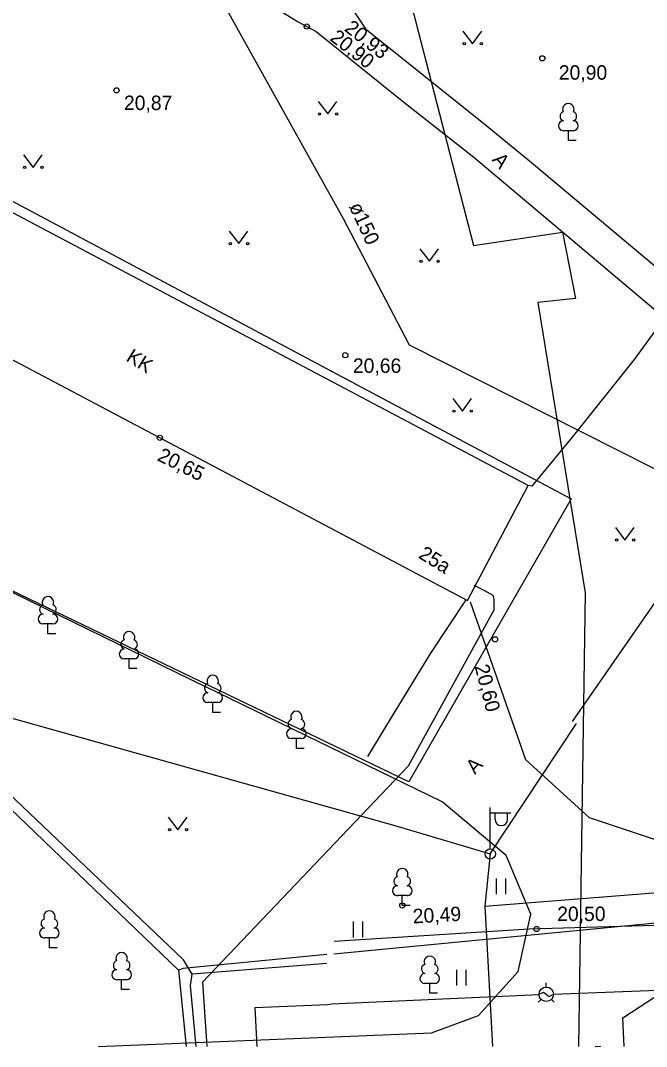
# Model space of a CAD drawing. Extents: x 714038 to 714279, y 6589845 to 6590041.
# Drawn here: x 714075.51 to 714105.82, y 6589845.18 to 6589894.87 of the extents above; entities that cross this region are included whole.
import ezdxf

# ---------------------------------------------------------------- set-up
doc = ezdxf.new("R2010")
doc.units = 0
for name, color, linetype in [('HALJASTUS', 7, 'Continuous'), ('HOONE', 7, 'Continuous'), ('KORGUS', 7, 'Continuous'), ('MPKAABEL', 7, 'Continuous'), ('POST', 7, 'Continuous'), ('PUU', 7, 'Continuous'), ('SITRASS', 7, 'Continuous'), ('TEE', 7, 'Continuous'), ('TORU NR', 7, 'Continuous'), ('TTRASS', 7, 'Continuous'), ('Слой 1', 7, 'Continuous')]:
    doc.layers.add(name, color=color, linetype=linetype)

msp = doc.modelspace()

# ---------------------------------------------------------------- linework, layer by layer
at = {"layer": 'HALJASTUS'}
for p, q in [((714096.937, 6589894.357), (714097.4, 6589893.75)), ((714097.4, 6589893.75), (714097.846, 6589894.357)), ((714089.927, 6589890.957), (714090.39, 6589890.35)), ((714090.39, 6589890.35), (714090.836, 6589890.957)), ((714075.657, 6589888.367), (714076.12, 6589887.76)), ((714076.12, 6589887.76), (714076.566, 6589888.367)), ((714085.617, 6589884.677), (714086.08, 6589884.07)), ((714086.08, 6589884.07), (714086.526, 6589884.677)), ((714094.847, 6589883.817), (714095.31, 6589883.21)), ((714095.31, 6589883.21), (714095.756, 6589883.817)), ((714096.447, 6589876.557), (714096.91, 6589875.95)), ((714096.91, 6589875.95), (714097.356, 6589876.557)), ((714104.317, 6589870.317), (714104.78, 6589869.71)), ((714104.78, 6589869.71), (714105.226, 6589870.317)), ((714082.667, 6589856.287), (714083.13, 6589855.68)), ((714083.13, 6589855.68), (714083.576, 6589856.287)), ((714098.549, 6589853.318), (714098.549, 6589852.557)), ((714099.004, 6589853.318), (714099.004, 6589852.557)), ((714091.624, 6589851.226), (714091.624, 6589850.465)), ((714092.079, 6589851.226), (714092.079, 6589850.465)), ((714096.617, 6589848.892), (714096.617, 6589848.131)), ((714097.072, 6589848.892), (714097.072, 6589848.131))]:
    msp.add_line(p, q, dxfattribs=at)
msp.add_lwpolyline([(714092.33, 6589859.23), (714093.48, 6589861.11), (714095.38, 6589864.23), (714097.1, 6589866.81)], dxfattribs=at)
for centre in [(714096.999, 6589893.75), (714097.828, 6589893.75), (714089.989, 6589890.35), (714090.818, 6589890.35), (714075.719, 6589887.76), (714076.548, 6589887.76), (714085.679, 6589884.07), (714086.508, 6589884.07), (714094.909, 6589883.21), (714095.738, 6589883.21), (714096.509, 6589875.95), (714097.338, 6589875.95), (714104.379, 6589869.71), (714105.208, 6589869.71), (714082.729, 6589855.68), (714083.558, 6589855.68)]:
    msp.add_circle(centre, 0.055, dxfattribs=at)
at = {"layer": 'HOONE'}
for p, q in [((714100.973, 6589848.058), (714100.973, 6589848.255)), ((714100.623, 6589847.706), (714100.834, 6589847.812)), ((714100.834, 6589847.812), (714101.112, 6589847.604)), ((714101.112, 6589847.604), (714101.323, 6589847.71)), ((714100.726, 6589847.461), (714100.586, 6589847.321)), ((714101.22, 6589847.461), (714101.36, 6589847.321))]:
    msp.add_line(p, q, dxfattribs=at)
for points in [[(714078.09, 6589905.88), (714078.71, 6589905.51), (714082.61, 6589900.59), (714091.14, 6589885.28), (714094.34, 6589879.16), (714119.53, 6589866.44), (714125.14, 6589863.75), (714152.793, 6589849.501)], [(714067.9, 6589889.39), (714064.95, 6589883.81), (714097.15, 6589866.78), (714100.1, 6589872.35), (714067.9, 6589889.39)], [(714101.323, 6589847.721), (714118.1, 6589848.36), (714137.92, 6589849.09), (714152.448, 6589849.676)], [(714086.964, 6589845.18), (714086.87, 6589847.07), (714090.375, 6589847.215), (714090.58, 6589847.238), (714100.623, 6589847.692)]]:
    msp.add_lwpolyline(points, dxfattribs=at)
msp.add_circle((714100.973, 6589847.708), 0.35, dxfattribs=at)
at = {"layer": 'KORGUS'}
for centre in [(714089.38, 6589894.58), (714100.78, 6589893.04), (714080.16, 6589891.49), (714091.24, 6589878.66), (714082.26, 6589874.66), (714098.49, 6589864.9), (714094, 6589852.01), (714100.5, 6589850.87)]:
    msp.add_circle(centre, 0.125, dxfattribs=at)
at = {"layer": 'MPKAABEL'}
for points in [[(714119.52, 6589886.24), (714109.49, 6589871.38), (714102.223, 6589860.927)], [(714083.83, 6589848.69), (714083.41, 6589849.38), (714068.79, 6589863.28), (714053.53, 6589878.23)], [(714097.46, 6589867.53), (714097.95, 6589867.28), (714098.39, 6589867.04), (714098.44, 6589866.84), (714098.44, 6589866.65), (714098.44, 6589866.31), (714094.29, 6589858.75), (714084.33, 6589848.3), (714084.53, 6589845.18)], [(714058.96, 6589865.61), (714093.643, 6589855.885), (714098.262, 6589854.503), (714102.429, 6589860.826)], [(714097.99, 6589851.98), (714132.72, 6589854.72), (714139.52, 6589857.18), (714167.494, 6589858.459)], [(714098.262, 6589854.503), (714097.99, 6589851.98), (714098.373, 6589845.18)], [(714138.276, 6589846.432), (714137.631, 6589851.226), (714130.578, 6589851.054), (714119.479, 6589851.364), (714110.093, 6589851.16), (714100.14, 6589850.863), (714090.701, 6589850.272)], [(714090.352, 6589849.197), (714083.83, 6589848.69)], [(714084.012, 6589845.18), (714083.74, 6589848.14), (714083.83, 6589848.69)]]:
    msp.add_lwpolyline(points, dxfattribs=at)
at = {"layer": 'POST'}
for p, q in [((714098.262, 6589854.753), (714098.262, 6589856.753)), ((714098.262, 6589856.503), (714099.262, 6589856.503)), ((714098.489, 6589856.182), (714098.489, 6589856.503)), ((714099.101, 6589856.182), (714099.101, 6589856.503))]:
    msp.add_line(p, q, dxfattribs=at)
for radius in [0.25, 0.0234]:
    msp.add_circle((714098.262, 6589854.503), radius, dxfattribs=at)
msp.add_arc((714098.795, 6589856.182), 0.306, 180, 0, dxfattribs=at)
at = {"layer": 'PUU'}
for p, q in [((714102.28, 6589889.535), (714101.8, 6589889.535)), ((714102.04, 6589889.06), (714102.04, 6589889.535)), ((714102.42, 6589889.06), (714102.04, 6589889.06)), ((714077.08, 6589865.645), (714076.6, 6589865.645)), ((714076.84, 6589865.17), (714076.84, 6589865.645)), ((714077.22, 6589865.17), (714076.84, 6589865.17)), ((714081.01, 6589863.955), (714080.53, 6589863.955)), ((714080.77, 6589863.48), (714080.77, 6589863.955)), ((714081.15, 6589863.48), (714080.77, 6589863.48)), ((714085.06, 6589861.835), (714084.58, 6589861.835)), ((714084.82, 6589861.36), (714084.82, 6589861.835)), ((714085.2, 6589861.36), (714084.82, 6589861.36)), ((714089.11, 6589860.095), (714088.63, 6589860.095)), ((714088.87, 6589859.62), (714088.87, 6589860.095)), ((714089.25, 6589859.62), (714088.87, 6589859.62)), ((714094.24, 6589852.485), (714093.76, 6589852.485)), ((714094, 6589852.01), (714094, 6589852.485)), ((714094.38, 6589852.01), (714094, 6589852.01)), ((714077.15, 6589850.435), (714076.67, 6589850.435)), ((714076.91, 6589849.96), (714076.91, 6589850.435)), ((714077.29, 6589849.96), (714076.91, 6589849.96)), ((714080.65, 6589848.415), (714080.17, 6589848.415)), ((714080.41, 6589847.94), (714080.41, 6589848.415)), ((714095.57, 6589848.235), (714095.09, 6589848.235)), ((714095.33, 6589847.76), (714095.33, 6589848.235)), ((714080.79, 6589847.94), (714080.41, 6589847.94)), ((714095.71, 6589847.76), (714095.33, 6589847.76))]:
    msp.add_line(p, q, dxfattribs=at)
for centre, radius, start, end in [((714101.87, 6589890.233), 0.233, 109.0217, 253.1415), ((714102.04, 6589890.58), 0.277, 332.5799, 207.4201), ((714102.21, 6589890.233), 0.233, 286.8508, 70.9859), ((714101.803, 6589889.772), 0.238, 90.0016, 269.3953), ((714102.277, 6589889.772), 0.238, 270.6047, 89.9984), ((714076.84, 6589866.69), 0.277, 332.5799, 207.4201), ((714076.603, 6589865.882), 0.238, 90.0016, 269.3953), ((714076.67, 6589866.343), 0.233, 109.0217, 253.1415), ((714077.01, 6589866.343), 0.233, 286.8508, 70.9859), ((714077.077, 6589865.882), 0.238, 270.6047, 89.9984), ((714080.77, 6589865), 0.277, 332.5799, 207.4201), ((714080.6, 6589864.653), 0.233, 109.0217, 253.1415), ((714080.94, 6589864.653), 0.233, 286.8508, 70.9859), ((714080.533, 6589864.192), 0.238, 90.0016, 269.3953), ((714081.007, 6589864.192), 0.238, 270.6047, 89.9984), ((714084.82, 6589862.88), 0.277, 332.5799, 207.4201), ((714084.65, 6589862.533), 0.233, 109.0217, 253.1415), ((714084.99, 6589862.533), 0.233, 286.8508, 70.9859), ((714084.583, 6589862.072), 0.238, 90.0016, 269.3953), ((714085.057, 6589862.072), 0.238, 270.6047, 89.9984), ((714088.87, 6589861.14), 0.277, 332.5799, 207.4201), ((714088.7, 6589860.793), 0.233, 109.0217, 253.1415), ((714089.04, 6589860.793), 0.233, 286.8508, 70.9859), ((714088.633, 6589860.332), 0.238, 90.0016, 269.3953), ((714089.107, 6589860.332), 0.238, 270.6047, 89.9984), ((714094, 6589853.53), 0.277, 332.5799, 207.4201), ((714093.83, 6589853.183), 0.233, 109.0217, 253.1415), ((714094.17, 6589853.183), 0.233, 286.8508, 70.9859), ((714093.763, 6589852.722), 0.238, 90.0016, 269.3953), ((714094.237, 6589852.722), 0.238, 270.6047, 89.9984), ((714076.91, 6589851.48), 0.277, 332.5799, 207.4201), ((714076.74, 6589851.133), 0.233, 109.0217, 253.1415), ((714077.08, 6589851.133), 0.233, 286.8508, 70.9859), ((714076.673, 6589850.672), 0.238, 90.0016, 269.3953), ((714077.147, 6589850.672), 0.238, 270.6047, 89.9984), ((714080.41, 6589849.46), 0.277, 332.5799, 207.4201), ((714080.24, 6589849.113), 0.233, 109.0217, 253.1415), ((714080.58, 6589849.113), 0.233, 286.8508, 70.9859), ((714095.33, 6589849.28), 0.277, 332.5799, 207.4201), ((714080.173, 6589848.652), 0.238, 90.0016, 269.3953), ((714080.647, 6589848.652), 0.238, 270.6047, 89.9984), ((714095.093, 6589848.472), 0.238, 90.0016, 269.3953), ((714095.16, 6589848.933), 0.233, 109.0217, 253.1415), ((714095.5, 6589848.933), 0.233, 286.8508, 70.9859), ((714095.567, 6589848.472), 0.238, 270.6047, 89.9984)]:
    msp.add_arc(centre, radius, start, end, dxfattribs=at)
at = {"layer": 'SITRASS'}
for points in [[(714090.677, 6589849.662), (714113.82, 6589851.89), (714129.13, 6589853.35), (714149.88, 6589856.55), (714152.63, 6589857), (714152.96, 6589857.28), (714152.96, 6589861.27), (714152.34, 6589878.74), (714151.806, 6589893.533), (714150.243, 6589893.464)], [(714051.92, 6589875.53), (714052.13, 6589875.9), (714052.47, 6589876.55), (714052.93, 6589877.01), (714053.29, 6589877.1), (714053.93, 6589877.01), (714054.62, 6589876.27), (714083.17, 6589848.87)], [(714090.347, 6589849.63), (714083.39, 6589848.96), (714083.17, 6589848.87)], [(714083.17, 6589848.87), (714083.534, 6589845.18)]]:
    msp.add_lwpolyline(points, dxfattribs=at)
at = {"layer": 'TEE'}
for points in [[(714086.51, 6589941.37), (714087.32, 6589924.76), (714087.38, 6589920.12), (714087.72, 6589911.79), (714087.85, 6589909.44), (714088.28, 6589906.16), (714091.41, 6589895.68), (714092.21, 6589894.47), (714097.93, 6589889.9), (714100.25, 6589887.99), (714107.35, 6589882.05), (714107.55, 6589881.95), (714107.8, 6589881.95), (714108.25, 6589882.4), (714112.03, 6589885.67), (714115.5, 6589888.54), (714117.37, 6589890.21), (714119.68, 6589892.17), (714121.69, 6589893.77), (714119.92, 6589931.6), (714120.33, 6589931.74), (714133.63, 6589932.2)], [(714081.84, 6589898.71), (714086.19, 6589896.53), (714088.93, 6589894.83), (714089.83, 6589894.34), (714094.07, 6589890.92), (714097.47, 6589888.25), (714106.78, 6589880.4), (714106.54, 6589880.24), (714105.23, 6589878.45), (714102.22, 6589874.69), (714100.28, 6589872.32), (714100.1, 6589872.35)], [(714106.49, 6589877.73), (714107.08, 6589878.66), (714107.57, 6589879.1), (714107.81, 6589879.2), (714108.06, 6589879.15), (714108.45, 6589878.81), (714122.933, 6589865.663), (714123.28, 6589856.879), (714117.613, 6589854.595), (714109.818, 6589854.018), (714103.059, 6589856.247), (714099.978, 6589859.069), (714097.302, 6589866.694)], [(714070.204, 6589869.569), (714084.491, 6589862.601)], [(714079.29, 6589845.18), (714095.409, 6589845.833), (714097.686, 6589846.678), (714099.614, 6589848.817), (714100.217, 6589851.595), (714099.031, 6589854.432), (714095.932, 6589857.026), (714084.491, 6589862.601)], [(714104.748, 6589845.18), (714104.677, 6589846.572), (714109.57, 6589849.766), (714119.211, 6589850.115), (714119.462, 6589846.176)]]:
    msp.add_lwpolyline(points, dxfattribs=at)
at = {"layer": 'TTRASS'}
for points in [[(714092.49, 6589903.19), (714097.44, 6589883.98), (714101.75, 6589884.62), (714102.39, 6589881.41), (714100.56, 6589881.22), (714102.85, 6589867.15), (714102.756, 6589860.667), (714102.531, 6589845.18)], [(714103.337, 6589845.18), (714103.58, 6589845.2), (714103.58, 6589845.18)]]:
    msp.add_lwpolyline(points, dxfattribs=at)
at = {"layer": 'Слой 1'}
msp.add_lwpolyline([(714102.17, 6589871.7), (714094.32, 6589857.99), (714053.54, 6589877.63), (714060.68, 6589893.81)], close=True, dxfattribs=at)

# ---------------------------------------------------------------- texts
at = {"layer": 'HOONE'}
for s, p in [('KK', (714080.579, 6589878.42)), ('25a', (714094.736, 6589868.872))]:
    msp.add_text(s, height=0.7, rotation=328.2666, dxfattribs=at).set_placement(p)
at = {"layer": 'KORGUS'}
for s, rotation, p in [('20,90', 321.8334, (714090.45, 6589893.947)), ('20,93', 321.8334, (714091.153, 6589894.407)), ('20,65', 333.5159, (714082.093, 6589873.587)), ('20,60', 284.4774, (714097.496, 6589863.596)), ('20,49', 3.1114, (714094.527, 6589851.138))]:
    msp.add_text(s, height=0.7, rotation=rotation, dxfattribs=at).set_placement(p)
for s, p in [('20,90', (714101.579, 6589892.005)), ('20,87', (714080.521, 6589890.535)), ('20,66', (714091.608, 6589877.805)), ('20,50', (714101.499, 6589851.255))]:
    msp.add_text(s, height=0.7, dxfattribs=at).set_placement(p)
at = {"layer": 'TEE'}
for rotation, p in [(310.4162, (714098.32, 6589888.109)), (46.9276, (714097.517, 6589858.329))]:
    msp.add_text('A', height=0.7, rotation=rotation, dxfattribs=at).set_placement(p)
at = {"layer": 'TORU NR'}
msp.add_text('ø150', height=0.7, rotation=294.5451, dxfattribs=at).set_placement((714091.407, 6589885.875))

doc.saveas('drawing.dxf')
